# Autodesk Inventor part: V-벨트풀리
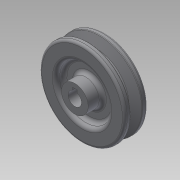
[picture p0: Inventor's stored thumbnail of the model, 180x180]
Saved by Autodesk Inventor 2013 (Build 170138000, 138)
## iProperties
Created: 2015-02
Part Number: V-벨트풀리
Material: 일반
Document SubType Name: Modeling
Designer: Administrator
Density: 1 g/cm^3
Author: Administrator
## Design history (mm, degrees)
sketch "스케치1"
  geometry: L1 (0, 0)-(25, 0); L2 (0, 0)-(0, 11); L3 (0, 11)-(6, 11); L4 (6, 11)-(6, 21.5); L5 (6, 21.5)-(0, 21.5); L6 (0, 21.5)-(0, 35.2); L7 (0, 35.2)-(4.675, 35.2); L8 (4.675, 35.2)-(7.426, 26.2); L9 (7.426, 26.2)-(11.574, 26.2); L10 (11.574, 26.2)-(14.325, 35.2); L11 (14.325, 35.2)-(19, 35.2); L12 (19, 35.2)-(19, 21.5); L13 (19, 21.5)-(13, 21.5); L14 (13, 21.5)-(13, 11); L15 (13, 11)-(25, 11); L16 (25, 11)-(25, 0); L17 (5.5, 32.5)-(13.5, 32.5); 1 further point
  constraints: 34 end point, 8 perpendicular, 5 equal length, 5 parallel, 2 collinear, 2 point on line, 1 horizontal, 1 midpoint, 1 vertical alignment
  dimensions: "d0" = 25 distance of L1.start L1.end; "d1" = 43 diameter of L5 L1; "d2" = 65 diameter of L17 L1; "d3" = 19 distance between parallel lines of L12 L6; "d4" = 8 distance of L17.start L17.end; "d5" = 34 deg angle of L10 L8; "d6" = 6 distance between parallel lines of L4 L2; "d7" = 6.3 distance between parallel lines of L17 L9; "d8" = 2.7 distance between parallel lines of L11 L17; "d9" = 22 diameter of L15 L1
revolve "회전1" sketch "스케치1" stored, may be unused: angle "d10" = 90 deg
sketch "스케치2"
  geometry: L1 (-2, 7.3)-(2, 7.3); L2 (-2, 7.3)-(-2, 5.123); L3 (2, 7.3)-(2, 5.123); C1 r 11 at (0, 0) reference; A1 r 5.5 centre (0, 0) between (-2, 5.123) and (2, 5.123); 2 further points
  constraints: 6 end point, 3 point on circle, 2 vertical alignment, 1 centre point, 1 coincident, 1 horizontal, 1 midpoint, 1 parallel, 1 perpendicular
  dimensions: "d11" = 11 diameter of A1; "d13" = 4 distance of L1.start L1.end; "d14" = 12.8 distance from line of point (0, -5.5) L1
extrude "돌출1" cut sketch "스케치2" stored distance "d15" = 10; taper "d16" = 0 deg
fillet "모깎기1" dims "d17" = 2
fillet "모깎기2" dims "d18" = 0.5
fillet "모깎기3" dims "d19" = 1
fillet "모깎기4" dims "d20" = 3
fillet "모깎기5" dims "d21" = 3
fillet "모깎기6" dims "d22" = 3
node "솔리드1"
